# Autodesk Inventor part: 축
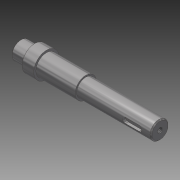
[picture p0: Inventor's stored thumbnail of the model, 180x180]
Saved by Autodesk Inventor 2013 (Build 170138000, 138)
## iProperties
Created: 2015-09
Part Number: 축
Material: 강철, 연강
Document SubType Name: Modeling
Designer: mduedu
Density: 7.86 g/cm^3
Mass: 263.424 g
Surface Area: 86.4309 cm^2
Volume: 33.5145 cm^3
Author: mduedu
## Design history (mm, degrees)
sketch "스케치1"
  geometry: L1 (-66.5, 0)-(66.5, 0); L2 (-66.5, 0)-(-66.5, 8.5); L3 (-66.5, 8.5)-(-51.5, 8.5); L4 (-51.5, 8.5)-(-51.5, 12); L5 (-51.5, 12)-(-40.5, 12); L6 (-40.5, 12)-(-40.5, 10); L7 (-40.5, 10)-(-3.5, 10); L8 (-3.5, 10)-(-3.5, 8.5); L9 (-3.5, 8.5)-(66.5, 8.5); L10 (66.5, 8.5)-(66.5, 0); 2 further points
  constraints: 20 end point, 5 parallel, 2 horizontal, 2 perpendicular, 1 coincident, 1 midpoint, 1 vertical
  dimensions: "d0" = 133 distance of L1.start L1.end; "d2" = 11 distance of L4.end L5.end; "d3" = 37 distance of L6.end L7.end; "d4" = 70 distance of L8.end L9.end; "d5" = 17 diameter of L3 L1; "d6" = 17 diameter of L9 L1; "d7" = 20 diameter of L7 L1; "d8" = 24 diameter of L5 L1
revolve "회전1" sketch "스케치1" stored, may be unused: angle "d9" = 90 deg
node "작업 평면1"
sketch "스케치2"
  geometry: L1 (10.5, 2.5)-(23.5, 2.5); L2 (23.5, -2.5)-(10.5, -2.5); L3 (10.5, 2.5)-(23.5, -2.5); L4 (23.5, 2.5)-(10.5, -2.5); L5 (35, -8.5)-(35, 8.5) reference; A1 r 2.5 centre (10.5, 0) between (10.5, 2.5) and (10.5, -2.5); A2 r 2.5 centre (23.5, 0) between (23.5, -2.5) and (23.5, 2.5); 2 further points
  constraints: 8 end point, 4 point on circle, 4 tangent, 2 centre point, 2 midpoint, 1 horizontal, 1 horizontal alignment, 1 parallel
  dimensions: "d10" = 18 dimension on A2 A1; "d12" = 9 distance edge to line of A2 L5; "d13" = 5 distance between parallel lines of L2 L1
extrude "돌출1" cut sketch "스케치2" distance "d14" = 3; taper "d15" = 0 deg
node "작업 평면2"
sketch "스케치4"
  geometry: L1 (9.5, -3)-(-6.5, -3); L2 (-6.5, 3)-(9.5, 3); L3 (-18.5, 10)-(-18.5, -10) reference; A1 r 3 centre (-6.5, 0) between (-6.5, 3) and (-6.5, -3); A2 r 3 centre (9.5, 0) between (9.5, -3) and (9.5, 3); 1 further point
  constraints: 4 end point, 4 point on circle, 4 tangent, 2 centre point, 1 horizontal, 1 horizontal alignment, 1 parallel
  dimensions: "d16" = 22 dimension on A1 A2; "d18" = 6 distance between parallel lines of L2 L1; "d19" = 9 distance edge to line of A1 L3
extrude "돌출2" cut sketch "스케치4" distance "d20" = 3.5; taper "d21" = 0 deg
sketch "스케치5"
  geometry: L1 (-3.5, 8.5)-(66.5, 8.5) reference; L2 (-3.5, -8.5)-(66.5, -8.5) reference; L3 (40.5, 8.5)-(40.5, -8.5); L4 (40.5, -6.5)-(38.5, -8.5); L5 (40.5, -8.5)-(38.5, -8.5); L6 (40.5, -8.5)-(40.5, -6.5); L7 (-3.5, -10)-(-3.5, 10) reference; 1 further point
  constraints: 8 end point, 4 point on line, 1 collinear, 1 perpendicular
  dimensions: "d22" = 4 diameter of L4.end L3; "d24" = 45 deg angle of L3 L4; "d26" = 44 distance between parallel lines of L3 L7
revolve "회전2" sketch "스케치5" stored, may be unused: angle "d27" = 90 deg
chamfer "모따기1" distance "d28" = 1; stored, may be unused: second distance "d29" = 2, angle "d30" = 45 deg
sketch "스케치6"
  geometry: L1 (40.5, -6.5)-(38.5, -8.5) reference; L2 (40.5, -6.5)-(42.5, -8.5) reference; 2 further points
  constraints: 1 coincident
hole "구멍1" diameter "d33" = 4.917; stored, may be unused: countersink angle "d37" = 90 deg, drill point angle "d39" = 118 deg; dims "d34" = 12, "d35" = 4, "d36" = 2, "d38" = 15, "d42" = 10, "d43" = 10
node "솔리드1"
